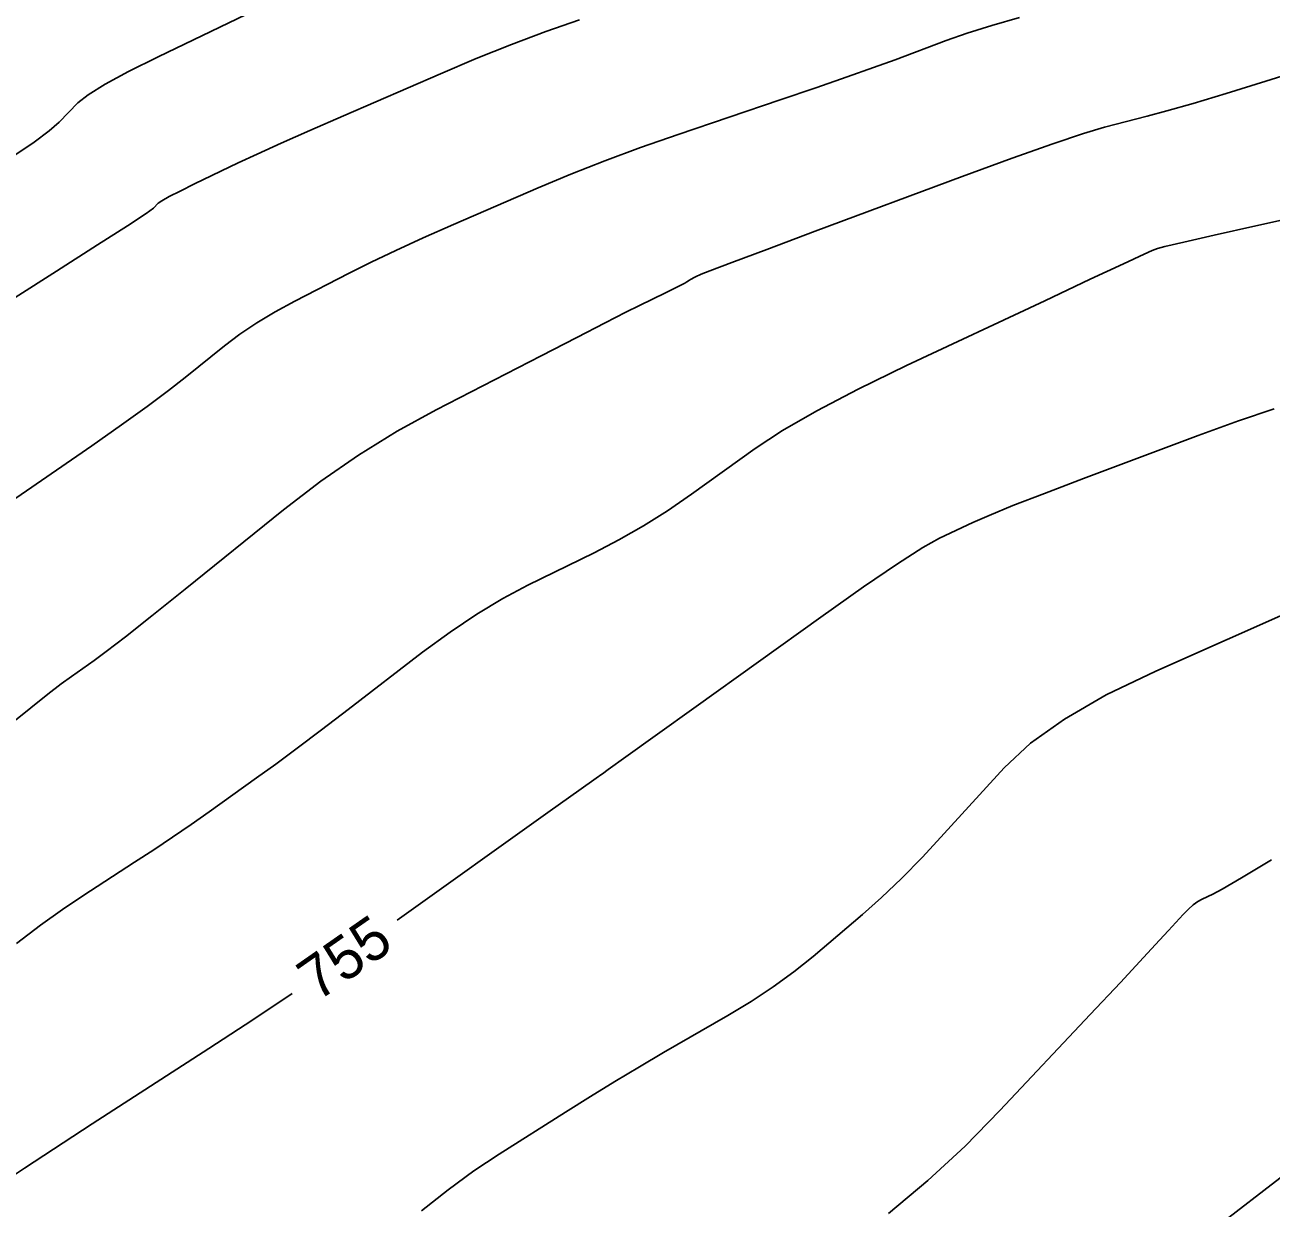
# Model space of a CAD drawing. Extents: x 2079879 to 2092887, y 778083 to 784051.
# Drawn here: x 2084644.1 to 2084725.9, y 781146.9 to 781224.5 of the extents above; entities that cross this region are included whole.
import ezdxf

# ---------------------------------------------------------------- set-up
doc = ezdxf.new("R2010")
doc.units = 0
doc.layers.add('DT_X_Contour_Major', color=7, linetype='Continuous')
doc.layers.add('DT_X_Contour_Minor', color=7, linetype='Continuous')

msp = doc.modelspace()

# ---------------------------------------------------------------- linework, layer by layer
at = {"layer": 'DT_X_Contour_Major'}
for points in [[(2084658.607, 781225.204), (2084652.829, 781222.428), (2084650.875, 781221.459), (2084649.346, 781220.631), (2084648.243, 781219.944), (2084647.565, 781219.4), (2084646.324, 781218.137), (2084645.685, 781217.575), (2084644.699, 781216.837), (2084643.365, 781215.921)], [(2084726.075, 781199.331), (2084723.733, 781198.54), (2084721.074, 781197.571), (2084713.56, 781194.75), (2084710.993, 781193.776), (2084708.925, 781192.97), (2084707.357, 781192.333), (2084706.288, 781191.864), (2084704.105, 781190.837), (2084703.005, 781190.225), (2084701.341, 781189.158), (2084699.115, 781187.636), (2084696.325, 781185.66), (2084688.134, 781179.785), (2084685.446, 781177.857), (2084683.526, 781176.479), (2084682.372, 781175.652), (2084681.985, 781175.375), (2084681.976, 781175.371), (2084681.973, 781175.369), (2084681.97, 781175.367), (2084681.966, 781175.365), (2084681.962, 781175.362), (2084681.953, 781175.354), (2084681.574, 781175.084), (2084680.443, 781174.277), (2084678.562, 781172.935), (2084668.504, 781165.76)], [(2084661.614, 781160.955), (2084659.042, 781159.226), (2084656.155, 781157.335), (2084648.501, 781152.388), (2084645.956, 781150.736), (2084644.06, 781149.489), (2084642.814, 781148.647), (2084642.217, 781148.211), (2084641.49, 781147.587), (2084641.19, 781147.336), (2084640.835, 781147.049), (2084640.424, 781146.727)]]:
    msp.add_lwpolyline(points, dxfattribs=at)
at = {"layer": 'DT_X_Contour_Minor'}
for points in [[(2084680.483, 781224.861), (2084678.274, 781224.085), (2084676.015, 781223.236), (2084673.708, 781222.313), (2084671.351, 781221.317), (2084665.002, 781218.562), (2084662.784, 781217.594), (2084660.893, 781216.755), (2084659.328, 781216.045), (2084658.089, 781215.464), (2084655.222, 781214.087), (2084654.266, 781213.62), (2084653.55, 781213.252), (2084653.073, 781212.984), (2084652.836, 781212.815), (2084652.524, 781212.497), (2084652.038, 781212.149), (2084650.817, 781211.344), (2084648.859, 781210.081), (2084646.165, 781208.361), (2084637.999, 781203.165)], [(2084709.357, 781225.006), (2084707.53, 781224.482), (2084705.93, 781223.979), (2084704.554, 781223.498), (2084701.186, 781222.242), (2084699.768, 781221.724), (2084698.037, 781221.112), (2084695.995, 781220.405), (2084693.642, 781219.603), (2084686.95, 781217.338), (2084684.494, 781216.482), (2084682.145, 781215.613), (2084679.902, 781214.73), (2084677.767, 781213.833), (2084672.213, 781211.424), (2084670.224, 781210.547), (2084668.42, 781209.724), (2084666.801, 781208.954), (2084665.368, 781208.238), (2084661.795, 781206.398), (2084660.501, 781205.697), (2084659.301, 781204.974), (2084658.195, 781204.228), (2084657.182, 781203.461), (2084654.607, 781201.383), (2084653.499, 781200.519), (2084652.106, 781199.485), (2084650.43, 781198.281), (2084648.469, 781196.906), (2084642.862, 781193.014)], [(2084733.086, 781223.186), (2084725.525, 781220.835), (2084722.912, 781220.03), (2084720.744, 781219.377), (2084719.021, 781218.877), (2084717.742, 781218.529), (2084714.926, 781217.805), (2084713.551, 781217.399), (2084711.536, 781216.724), (2084708.882, 781215.781), (2084705.59, 781214.569), (2084695.957, 781210.979), (2084692.779, 781209.793), (2084690.469, 781208.927), (2084689.028, 781208.381), (2084688.455, 781208.156), (2084688.086, 781207.982), (2084687.957, 781207.92), (2084687.849, 781207.864), (2084687.76, 781207.813), (2084687.691, 781207.768), (2084687.535, 781207.656), (2084687.403, 781207.579), (2084687.125, 781207.435), (2084686.7, 781207.222), (2084686.129, 781206.941), (2084684.412, 781206.101), (2084683.525, 781205.659), (2084682.154, 781204.963), (2084680.298, 781204.014), (2084677.958, 781202.811), (2084671.07, 781199.266), (2084668.506, 781197.858), (2084665.983, 781196.294), (2084663.501, 781194.574), (2084661.058, 781192.698), (2084654.597, 781187.487), (2084652.407, 781185.729), (2084650.683, 781184.362), (2084649.424, 781183.386), (2084648.631, 781182.802), (2084647.138, 781181.765), (2084646.468, 781181.278), (2084645.579, 781180.591), (2084644.47, 781179.707), (2084643.142, 781178.624)], [(2084733.159, 781213.181), (2084724.872, 781211.329), (2084722.137, 781210.715), (2084720.148, 781210.264), (2084718.904, 781209.973), (2084718.404, 781209.845), (2084718.067, 781209.718), (2084717.531, 781209.477), (2084716.177, 781208.847), (2084714.003, 781207.83), (2084711.011, 781206.424), (2084701.941, 781202.159), (2084698.769, 781200.619), (2084696.056, 781199.198), (2084693.803, 781197.896), (2084692.008, 781196.714), (2084687.834, 781193.72), (2084686.261, 781192.638), (2084684.672, 781191.637), (2084683.067, 781190.718), (2084681.445, 781189.88), (2084677.099, 781187.753), (2084675.444, 781186.879), (2084673.739, 781185.853), (2084671.983, 781184.674), (2084670.177, 781183.343), (2084665.293, 781179.589), (2084663.545, 781178.253), (2084661.961, 781177.06), (2084660.543, 781176.011), (2084659.29, 781175.104), (2084656.169, 781172.878), (2084654.986, 781172.044), (2084653.777, 781171.214), (2084652.542, 781170.387), (2084651.282, 781169.562), (2084647.886, 781167.368), (2084646.553, 781166.471), (2084645.099, 781165.428), (2084643.524, 781164.237)], [(2084727.662, 781186.27), (2084718.307, 781182.113), (2084715.054, 781180.546), (2084712.309, 781178.965), (2084710.074, 781177.369), (2084708.348, 781175.758), (2084704.423, 781171.441), (2084702.983, 781169.896), (2084701.607, 781168.497), (2084700.296, 781167.245), (2084699.049, 781166.139), (2084695.809, 781163.384), (2084694.548, 781162.367), (2084693.196, 781161.379), (2084691.752, 781160.422), (2084690.216, 781159.496), (2084685.998, 781157.066), (2084684.41, 781156.139), (2084682.809, 781155.18), (2084681.194, 781154.19), (2084679.566, 781153.169), (2084675.207, 781150.403), (2084673.552, 781149.298), (2084671.857, 781148.058), (2084670.12, 781146.681)], [(2084725.891, 781169.717), (2084723.934, 781168.543), (2084722.653, 781167.792), (2084722.049, 781167.462), (2084721.34, 781167.147), (2084721.063, 781166.995), (2084720.763, 781166.773), (2084720.44, 781166.484), (2084720.094, 781166.125), (2084719.141, 781165.077), (2084718.551, 781164.438), (2084717.496, 781163.305), (2084715.975, 781161.68), (2084713.989, 781159.563), (2084708.073, 781153.258), (2084705.781, 781150.931), (2084703.345, 781148.678), (2084700.763, 781146.5)], [(2084727.484, 781149.628), (2084721.482, 781144.99)]]:
    msp.add_lwpolyline(points, dxfattribs=at)

# ---------------------------------------------------------------- texts
at = {"layer": 'DT_X_Contour_Major'}
msp.add_text('755', height=2.8, rotation=34.88966, dxfattribs=at).set_placement((2084663.28, 781160.378))

doc.saveas('drawing.dxf')
